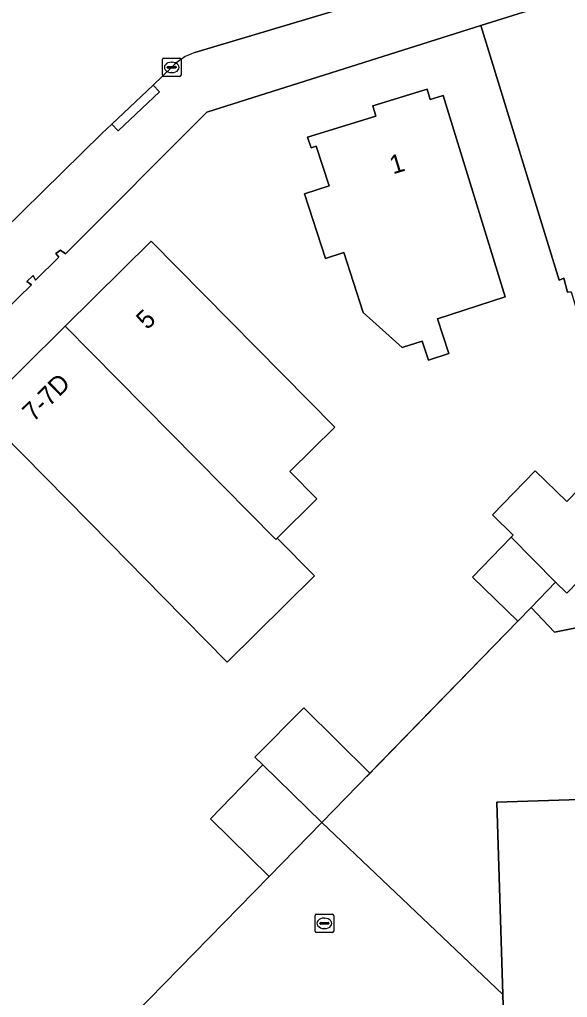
# Model space of a CAD drawing. Extents: x 161402 to 161933, y 381647 to 382315.
# Drawn here: x 161864.2 to 161893.8, y 382147.3 to 382200.1 of the extents above; entities that cross this region are included whole.
import ezdxf

# ---------------------------------------------------------------- set-up
doc = ezdxf.new("R2010")
doc.units = 0
for name, color, linetype in [('IMGEO_Erf', 7, 'Continuous'), ('IMGEO_Groenvoorziening', 7, 'Continuous'), ('IMGEO_Kolk', 7, 'Continuous'), ('IMGEO_Muur', 7, 'Continuous'), ('IMGEO_Pand', 7, 'Continuous'), ('IMGEO_Pand_nummerreeks', 7, 'Continuous'), ('IMGEO_Parkeervlak_open', 7, 'Continuous'), ('IMGEO_Rijbaan_lokaal_open', 7, 'Continuous'), ('IMGEO_Voetpad_open', 7, 'Continuous')]:
    doc.layers.add(name, color=color, linetype=linetype)

msp = doc.modelspace()

# ---------------------------------------------------------------- linework, layer by layer
at = {"layer": 'IMGEO_Erf'}
for points in [[(161893.95, 382185.368), (161893.75, 382185.352), (161893.564, 382186.105), (161893.312, 382186), (161889.081, 382199.745), (161888.053, 382199.426), (161874.289, 382195.061), (161866.643, 382187.422), (161866.387, 382187.627), (161866.133, 382187.442), (161866.29, 382187.249), (161865.037, 382186.002), (161864.902, 382186.245), (161864.566, 382185.921), (161864.813, 382185.757), (161863.347, 382184.324)], [(161869.551, 382145.549), (161877.656, 382153.823), (161874.475, 382156.943), (161877.306, 382159.843), (161876.878, 382160.259), (161879.518, 382162.929), (161883.09, 382159.398), (161891.072, 382167.601), (161888.622, 382169.982), (161890.713, 382172.133), (161890.821, 382172.244), (161889.704, 382173.33), (161892.015, 382175.707), (161893.719, 382174.051), (161896.507, 382176.919)]]:
    msp.add_lwpolyline(points, dxfattribs=at)
for points in [[(161879.562, 382190.666), (161880.88, 382191.094), (161880.186, 382193.236), (161879.912, 382193.147), (161879.727, 382193.718), (161883.417, 382194.854), (161883.25, 382195.399), (161886.175, 382196.3), (161886.342, 382195.755), (161887.049, 382195.972), (161890.398, 382185.096), (161886.738, 382183.91), (161887.343, 382182.043), (161886.247, 382181.689), (161885.914, 382182.714), (161884.825, 382182.361), (161882.73, 382184.25), (161881.679, 382187.494), (161880.694, 382187.175)], [(161869.076, 382171.783), (161862.004, 382178.944), (161866.64, 382183.522), (161871.276, 382188.1), (161881.186, 382178.065), (161878.765, 382175.668), (161880.219, 382174.195), (161878.082, 382172.084), (161880.095, 382170.045), (161875.385, 382165.394), (161871.914, 382168.909)]]:
    msp.add_lwpolyline(points, close=True, dxfattribs=at)
at = {"layer": 'IMGEO_Groenvoorziening'}
msp.add_lwpolyline([(161898.544, 382184.995), (161897.738, 382188.971), (161896.935, 382192.948), (161894.976, 382201.576), (161893.344, 382201.069), (161889.081, 382199.745), (161893.312, 382186), (161893.564, 382186.105), (161893.75, 382185.352), (161893.95, 382185.368), (161896.507, 382176.919), (161897.59, 382173.095), (161893.718, 382169.113), (161893.113, 382169.701), (161891.789, 382168.338), (161893.053, 382167.011), (161895.511, 382167.486), (161898.358, 382159.847), (161903.846, 382159.846), (161905.864, 382159.898), (161905.401, 382161.971)], dxfattribs=at)
at = {"layer": 'IMGEO_Kolk'}
for p, q in [((161871.889, 382197.057), (161871.889, 382197.909)), ((161871.964, 382197.983), (161872.816, 382197.983)), ((161872.377, 382197.763), (161872.402, 382197.763)), ((161872.89, 382197.909), (161872.89, 382197.057)), ((161872.148, 382197.477), (161872.148, 382197.489)), ((161872.586, 382197.44), (161872.188, 382197.44)), ((161872.191, 382197.526), (161872.589, 382197.526)), ((161872.4, 382197.203), (161872.375, 382197.203)), ((161872.632, 382197.489), (161872.632, 382197.477)), ((161872.816, 382196.983), (161871.964, 382196.983)), ((161880.131, 382150.87), (161880.131, 382151.722)), ((161880.206, 382151.796), (161881.058, 382151.796)), ((161881.132, 382151.722), (161881.132, 382150.87)), ((161880.39, 382151.29), (161880.39, 382151.302)), ((161880.828, 382151.253), (161880.43, 382151.253)), ((161880.433, 382151.339), (161880.831, 382151.339)), ((161880.619, 382151.576), (161880.644, 382151.576)), ((161880.874, 382151.302), (161880.874, 382151.29)), ((161881.058, 382150.796), (161880.206, 382150.796)), ((161880.642, 382151.016), (161880.617, 382151.016))]:
    msp.add_line(p, q, dxfattribs=at)
for points in [[(161871.889, 382197.057), (161871.889, 382197.909)], [(161871.964, 382197.983), (161872.816, 382197.983)], [(161872.89, 382197.909), (161872.89, 382197.057)], [(161872.816, 382196.983), (161871.964, 382196.983)], [(161880.131, 382150.87), (161880.131, 382151.722)], [(161880.206, 382151.796), (161881.058, 382151.796)], [(161881.132, 382151.722), (161881.132, 382150.87)], [(161881.058, 382150.796), (161880.206, 382150.796)]]:
    msp.add_lwpolyline(points, dxfattribs=at)
for centre, radius, start, end in [((161871.966, 382197.907), 0.0765, 91.552, 178.448), ((161871.966, 382197.907), 0.0765, 91.552, 178.448), ((161872.814, 382197.907), 0.0765, 1.552, 88.448), ((161872.814, 382197.907), 0.0765, 1.552, 88.448), ((161871.966, 382197.059), 0.0765, 181.552, 268.448), ((161871.966, 382197.059), 0.0765, 181.552, 268.448), ((161872.188, 382197.486), 0.0403, 85.8775, 175.7526), ((161872.185, 382197.476), 0.0366, 178.938, 274.7102), ((161872.589, 382197.483), 0.043, 264.8664, 352.4533), ((161872.593, 382197.488), 0.0386, 1.7309, 96.639), ((161872.814, 382197.059), 0.0765, 271.552, 358.448), ((161872.814, 382197.059), 0.0765, 271.552, 358.448), ((161880.208, 382151.72), 0.0765, 91.552, 178.448), ((161880.208, 382151.72), 0.0765, 91.552, 178.448), ((161881.056, 382151.72), 0.0765, 1.552, 88.448), ((161881.056, 382151.72), 0.0765, 1.552, 88.448), ((161880.43, 382151.299), 0.0403, 85.8775, 175.7526), ((161880.427, 382151.289), 0.0366, 178.938, 274.7102), ((161880.831, 382151.296), 0.043, 264.8664, 352.4533), ((161880.835, 382151.301), 0.0386, 1.7309, 96.639), ((161880.208, 382150.872), 0.0765, 181.552, 268.448), ((161880.208, 382150.872), 0.0765, 181.552, 268.448), ((161881.056, 382150.872), 0.0765, 271.552, 358.448), ((161881.056, 382150.872), 0.0765, 271.552, 358.448)]:
    msp.add_arc(centre, radius, start, end, dxfattribs=at)
for centre, major_axis, ratio, start_param, end_param in [((161872.376, 382197.483), (-0.387, 0.002), 0.722429, 4.712389, 7.853982), ((161872.401, 382197.483), (-0.39, 0.002), 0.717154, 1.570796, 4.712389), ((161880.618, 382151.296), (-0.387, 0.002), 0.722429, 4.712389, 7.853982), ((161880.643, 382151.296), (-0.39, 0.002), 0.717154, 1.570796, 4.712389)]:
    msp.add_ellipse(centre, major_axis=major_axis, ratio=ratio, start_param=start_param, end_param=end_param, dxfattribs=at)
at = {"layer": 'IMGEO_Muur'}
for points in [[(161882.914, 382159.218), (161891.072, 382167.601)], [(161877.656, 382153.823), (161869.551, 382145.549)]]:
    msp.add_lwpolyline(points, dxfattribs=at)
at = {"layer": 'IMGEO_Pand'}
for points in [[(161887.049, 382195.972), (161886.342, 382195.755), (161886.175, 382196.3), (161883.25, 382195.399), (161883.417, 382194.854), (161879.727, 382193.718), (161879.912, 382193.147), (161880.186, 382193.236), (161880.88, 382191.094), (161879.562, 382190.666), (161880.694, 382187.175), (161881.679, 382187.494), (161882.73, 382184.25), (161884.825, 382182.361), (161885.914, 382182.714), (161886.247, 382181.689), (161887.343, 382182.043), (161886.738, 382183.91), (161890.398, 382185.096)], [(161871.276, 382188.1), (161866.64, 382183.522), (161878.009, 382172.012), (161878.082, 382172.084), (161880.219, 382174.195), (161878.765, 382175.668), (161881.186, 382178.065)], [(161866.64, 382183.522), (161862.004, 382178.944), (161869.076, 382171.783), (161871.914, 382168.909), (161875.385, 382165.394), (161880.095, 382170.045), (161878.082, 382172.084), (161878.009, 382172.012)], [(161890.713, 382172.133), (161893.113, 382169.701), (161893.718, 382169.113), (161897.59, 382173.095), (161896.507, 382176.919), (161893.719, 382174.051), (161892.015, 382175.707), (161889.704, 382173.33), (161890.821, 382172.244)], [(161890.713, 382172.133), (161888.622, 382169.982), (161891.072, 382167.601), (161891.789, 382168.338), (161893.113, 382169.701)], [(161879.518, 382162.929), (161876.878, 382160.259), (161877.306, 382159.843), (161880.501, 382156.737), (161883.09, 382159.398)], [(161877.306, 382159.843), (161874.475, 382156.943), (161877.656, 382153.823), (161880.501, 382156.737)]]:
    msp.add_lwpolyline(points, close=True, dxfattribs=at)
at = {"layer": 'IMGEO_Parkeervlak_open'}
msp.add_lwpolyline([(161893.381, 382093.835), (161897.538, 382093.965), (161897.528, 382094.294), (161897.788, 382094.302), (161897.292, 382110.047), (161896.788, 382126.039), (161896.284, 382142.031), (161895.793, 382157.603), (161895.537, 382157.595), (161895.524, 382158.015), (161889.95, 382157.839), (161890.273, 382147.456), (161891.937, 382093.79)], close=True, dxfattribs=at)
at = {"layer": 'IMGEO_Rijbaan_lokaal_open'}
for points in [[(161873.633, 382198.285), (161886.979, 382202.286), (161891.451, 382203.647), (161892.577, 382203.997), (161891.355, 382208.844), (161886.363, 382207.312)], [(161861.128, 382186.583), (161868.607, 382193.906), (161869.157, 382194.426), (161871.375, 382196.525), (161872.392, 382197.487)], [(161891.943, 382093.602), (161891.937, 382093.79), (161890.273, 382147.456), (161880.501, 382156.737), (161877.656, 382153.823), (161869.551, 382145.549), (161859.667, 382135.458), (161860.18, 382134.346)]]:
    msp.add_lwpolyline(points, dxfattribs=at)
msp.add_arc((161874.534, 382195.52), 2.908, 108.0444, 137.44, dxfattribs=at)
at = {"layer": 'IMGEO_Voetpad_open'}
for points in [[(161886.979, 382202.286), (161873.633, 382198.285)], [(161857.746, 382179.014), (161858.236, 382179.449), (161858.103, 382179.58), (161858.378, 382179.885), (161858.604, 382179.691), (161863.062, 382184.049), (161862.906, 382184.222), (161863.181, 382184.507), (161863.347, 382184.324), (161864.813, 382185.757), (161864.566, 382185.921), (161864.902, 382186.245), (161865.037, 382186.002), (161866.29, 382187.249), (161866.133, 382187.442), (161866.387, 382187.627), (161866.643, 382187.422), (161874.289, 382195.061), (161888.053, 382199.426), (161889.081, 382199.745), (161893.344, 382201.069)], [(161872.392, 382197.487), (161871.375, 382196.525), (161871.717, 382196.161), (161869.499, 382194.062), (161869.157, 382194.426), (161868.607, 382193.906), (161861.128, 382186.583), (161851.645, 382177.23), (161851.993, 382176.872), (161849.775, 382174.684), (161849.427, 382175.042), (161845.418, 382171.09), (161845.727, 382170.776), (161833.874, 382159.097), (161833.565, 382159.411), (161826.896, 382152.873), (161824.294, 382150.346), (161819.797, 382145.977), (161816.704, 382142.95), (161813.317, 382139.636), (161811.571, 382137.928), (161810.829, 382138.748)]]:
    msp.add_lwpolyline(points, dxfattribs=at)
for points in [[(161871.375, 382196.525), (161869.157, 382194.426), (161869.499, 382194.062), (161871.717, 382196.161)], [(161895.511, 382167.486), (161893.053, 382167.011), (161891.789, 382168.338), (161891.072, 382167.601), (161883.09, 382159.398), (161880.501, 382156.737), (161890.273, 382147.456), (161889.95, 382157.839), (161895.524, 382158.015), (161906.731, 382158.368), (161905.864, 382159.898), (161903.846, 382159.846), (161898.358, 382159.847)]]:
    msp.add_lwpolyline(points, close=True, dxfattribs=at)
msp.add_arc((161874.534, 382195.52), 2.908, 108.0444, 137.44, dxfattribs=at)

# ---------------------------------------------------------------- texts
at = {"layer": 'IMGEO_Pand_nummerreeks'}
for s, rotation, p in [('1', 17.1104, (161884.337, 382191.706)), ('5', 44.6449, (161871.066, 382183.284)), ('7-7D', 44.6391, (161864.921, 382178.311))]:
    msp.add_text(s, height=1, rotation=rotation, dxfattribs=at).set_placement(p)

doc.saveas('drawing.dxf')
